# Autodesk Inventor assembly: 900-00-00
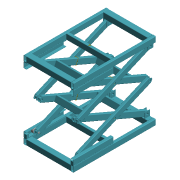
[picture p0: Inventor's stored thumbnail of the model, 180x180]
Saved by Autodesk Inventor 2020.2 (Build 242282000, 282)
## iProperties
Created: 2015-10
Part Number: 900-00-00
Document SubType Name: Assembly
Designer: F.Stasiak
Description: Podnośnik nożycowy
Catalog Web Link: www.expertbooks.pl
Manager: www.cadconsulting.pl
Company: Fabian Stasiak CAD Consulting
Author: F.Stasiak
Title: =<Part Number> - <Description>
Subject: Zbiór ćwiczeń. Autodesk Inventor 2020. Kurs Professional
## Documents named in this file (7)
- C:\2020_Kurs_Professional\R3 Dynamika\900-00-00.iam
- C:\2020_Kurs_Professional\R3 Dynamika\Komponenty_dyn\900-01-00.iam
- C:\2020_Kurs_Professional\R3 Dynamika\Komponenty_dyn\900-03-00.iam
- C:\2020_Kurs_Professional\R3 Dynamika\Komponenty_dyn\900-04-00.iam
- C:\2020_Kurs_Professional\R3 Dynamika\Komponenty_dyn\900-02-00.iam
- C:\2020_Kurs_Professional\R3 Dynamika\Komponenty_dyn\900-05-01.ipt
- C:\2020_Kurs_Professional\R3 Dynamika\Komponenty_dyn\900-06-01.ipt
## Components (12 placed, 6 different names)
1. 900-01-00:1 [sub-assembly] — PODNIESIENIE, Wstaw:10, Styczny:3
2. 900-02-00:1 [sub-assembly] — PODNIESIENIE, Wstaw:16, Wstaw:17
3. 900-03-00:1 [sub-assembly] — Wstaw:10, Wstaw:11, Wstaw:12, Wstaw:14
4. 900-03-00:2 [sub-assembly] — Wstaw:8, Wstaw:9, Wstaw:13, Wstaw:15, Wstaw:18
5. 900-04-00:2 [sub-assembly] — Wstaw:17, Wstaw:18
6. 900-04-00:6 [sub-assembly] — Wstaw:7, Wstaw:11
7. 900-04-00:4 [sub-assembly] — Wstaw:14, Wstaw:15, Wstaw:16
8. 900-04-00:5 [sub-assembly] — Wstaw:6, Wstaw:12, Wstaw:13
9. 900-05-01:1 — Wstaw:6
10. 900-05-01:2 — Wstaw:7, Styczny:3
11. 900-06-01:1 — Wstaw:9
12. 900-06-01:2 — Wstaw:8
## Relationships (15: Insert 13, Mate 1, Tangent 1)
- PODNIESIENIE [Mate]: 900-01-00:1 ↔ 900-02-00:1
- Styczny:3 [Tangent]: 900-01-00:1 ↔ 900-05-01:2
- Wstaw:6 [Insert]: 900-04-00:5 ↔ 900-05-01:1
- Wstaw:7 [Insert]: 900-04-00:6 ↔ 900-05-01:2
- Wstaw:8 [Insert]: 900-03-00:2 ↔ 900-06-01:2
- Wstaw:9 [Insert]: 900-03-00:2 ↔ 900-06-01:1
- Wstaw:10 [Insert]: 900-01-00:1 ↔ 900-03-00:1
- Wstaw:11 [Insert]: 900-03-00:1 ↔ 900-04-00:6
- Wstaw:12 [Insert]: 900-03-00:1 ↔ 900-04-00:5
- Wstaw:13 [Insert]: 900-03-00:2 ↔ 900-04-00:5
- Wstaw:14 [Insert]: 900-03-00:1 ↔ 900-04-00:4
- Wstaw:15 [Insert]: 900-03-00:2 ↔ 900-04-00:4
- Wstaw:16 [Insert]: 900-02-00:1 ↔ 900-04-00:4
- Wstaw:17 [Insert]: 900-02-00:1 ↔ 900-04-00:2
- Wstaw:18 [Insert]: 900-03-00:2 ↔ 900-04-00:2
